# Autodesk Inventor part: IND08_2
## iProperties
Created: 2006-01
Part Number: IND08_2
Document SubType Name: Modeling
Designer: DES
Author: DES
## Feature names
1. Extrude Block
2. Spotface Extrude Half [Extrusion]
3. Revolve Cav Form
